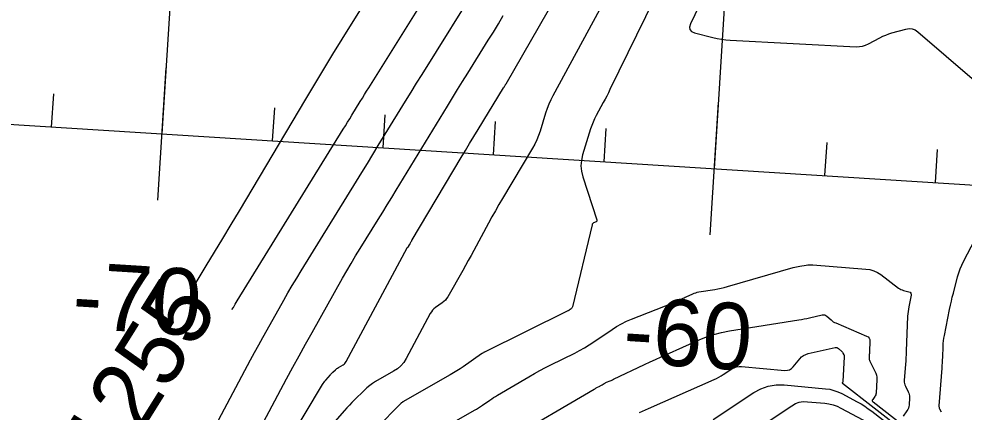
# Model space of a CAD drawing. Extents: x 658976 to 668721, y 639543 to 647196.
# Drawn here: x 662007.7 to 662093.1, y 641802.5 to 641838 of the extents above; entities that cross this region are included whole.
import ezdxf

# ---------------------------------------------------------------- set-up
doc = ezdxf.new("R2010")
doc.units = 0
for name, color, linetype in [('Ex_Contour Labels', 7, 'Continuous'), ('Ex_Major Contours', 7, 'Continuous'), ('Ex_Minor Contours', 7, 'Continuous'), ('R_Axis', 7, 'Continuous'), ('R_Axis Annot', 7, 'Continuous'), ('R_Grid', 7, 'Continuous')]:
    doc.layers.add(name, color=color, linetype=linetype)

msp = doc.modelspace()

# ---------------------------------------------------------------- linework, layer by layer
at = {"layer": 'Ex_Major Contours'}
for points in [[(662023.527, 641813.903), (662024.632, 641815.708), (662025.387, 641816.946), (662026.138, 641818.187), (662026.885, 641819.43), (662027.627, 641820.676), (662033.614, 641830.758), (662034.426, 641832.118), (662035.245, 641833.474), (662036.071, 641834.826), (662036.904, 641836.174), (662040.248, 641841.557)], [(662060.169, 641838.84), (662055.95, 641831.064), (662055.757, 641830.687), (662055.583, 641830.301), (662055.429, 641829.908), (662055.294, 641829.506), (662054.794, 641827.883), (662054.657, 641827.482), (662054.497, 641827.091), (662054.315, 641826.711), (662054.109, 641826.341), (662051.4, 641821.789), (662051.075, 641821.237), (662050.756, 641820.681), (662050.442, 641820.122), (662050.135, 641819.559), (662048.799, 641817.083), (662048.553, 641816.629), (662048.303, 641816.177), (662048.052, 641815.726), (662047.797, 641815.277), (662046.447, 641812.906), (662046.348, 641812.752), (662046.233, 641812.611), (662046.104, 641812.485), (662045.959, 641812.373), (662045.35, 641811.95), (662045.206, 641811.838), (662045.078, 641811.71), (662044.966, 641811.569), (662044.87, 641811.413), (662042.686, 641807.34), (662042.467, 641806.99), (662042.206, 641806.681), (662041.904, 641806.412), (662041.559, 641806.184), (662039.925, 641805.254), (662039.654, 641805.088), (662039.395, 641804.905), (662039.149, 641804.705), (662038.915, 641804.489), (662038.006, 641803.59), (662037.781, 641803.363), (662037.56, 641803.133), (662037.343, 641802.898), (662037.13, 641802.66), (662035.58, 641800.898)], [(662070.429, 641801.833), (662074.089, 641804.26), (662074.733, 641804.616), (662075.407, 641804.851), (662076.113, 641804.964), (662076.849, 641804.956), (662080.571, 641804.613), (662080.958, 641804.559), (662081.333, 641804.466), (662081.698, 641804.337), (662082.051, 641804.17), (662083.441, 641803.427), (662083.784, 641803.234), (662084.117, 641803.027), (662084.442, 641802.806), (662084.757, 641802.571), (662090.005, 641798.48)]]:
    msp.add_lwpolyline(points, dxfattribs=at)
at = {"layer": 'Ex_Minor Contours'}
for points in [[(662026.957, 641811.753), (662027.078, 641811.959), (662027.256, 641812.257), (662027.436, 641812.554), (662037.014, 641828.054), (662037.206, 641828.365), (662037.398, 641828.677), (662037.589, 641828.988), (662037.78, 641829.3), (662038.542, 641830.549), (662038.733, 641830.861), (662038.925, 641831.172), (662039.117, 641831.483), (662039.311, 641831.793), (662049.405, 641847.936)], [(662029.147, 641794.982), (662035.137, 641804.982), (662035.206, 641805.091), (662035.279, 641805.196), (662035.357, 641805.298), (662035.44, 641805.397), (662035.842, 641805.854), (662035.897, 641805.916), (662035.953, 641805.977), (662036.011, 641806.036), (662036.069, 641806.095), (662036.305, 641806.328), (662036.365, 641806.384), (662036.429, 641806.436), (662036.496, 641806.483), (662036.566, 641806.527), (662036.99, 641806.768), (662037.079, 641806.827), (662037.158, 641806.897), (662037.226, 641806.977), (662037.282, 641807.067), (662042.791, 641817.34), (662042.797, 641817.351), (662042.805, 641817.361), (662042.814, 641817.37), (662042.824, 641817.377), (662042.866, 641817.406), (662042.876, 641817.414), (662042.885, 641817.423), (662042.893, 641817.433), (662042.9, 641817.443), (662042.993, 641817.607), (662043.01, 641817.638), (662043.027, 641817.669), (662043.045, 641817.7), (662043.062, 641817.731), (662043.154, 641817.902), (662043.175, 641817.94), (662043.196, 641817.979), (662043.218, 641818.017), (662043.241, 641818.055), (662047.661, 641825.482), (662048.043, 641826.122), (662048.427, 641826.761), (662048.813, 641827.399), (662049.201, 641828.035), (662051.495, 641831.792), (662051.513, 641831.822), (662051.532, 641831.852), (662051.55, 641831.882), (662051.569, 641831.912), (662051.644, 641832.032), (662051.662, 641832.062), (662051.68, 641832.092), (662051.698, 641832.122), (662051.716, 641832.153), (662059.249, 641845.26)], [(662024.952, 641800.306), (662028.636, 641807.212), (662029.001, 641807.891), (662029.37, 641808.569), (662029.743, 641809.244), (662030.12, 641809.917), (662031.634, 641812.606), (662032.016, 641813.276), (662032.405, 641813.943), (662032.8, 641814.605), (662033.202, 641815.263), (662038.196, 641823.345), (662038.692, 641824.149), (662039.187, 641824.953), (662039.68, 641825.758), (662040.173, 641826.564), (662042.142, 641829.788), (662042.635, 641830.593), (662043.13, 641831.397), (662043.628, 641832.2), (662044.127, 641833.001), (662049.477, 641841.557)], [(662065.129, 641839.892), (662061.105, 641831.633), (662060.958, 641831.335), (662060.808, 641831.04), (662060.655, 641830.746), (662060.498, 641830.454), (662059.866, 641829.288), (662059.715, 641828.993), (662059.58, 641828.693), (662059.459, 641828.385), (662059.354, 641828.072), (662058.632, 641825.73), (662058.518, 641825.235), (662058.483, 641824.74), (662058.526, 641824.246), (662058.648, 641823.752), (662059.919, 641819.852), (662059.928, 641819.797), (662059.919, 641819.751), (662059.892, 641819.712), (662059.845, 641819.682), (662059.622, 641819.578), (662059.572, 641819.548), (662059.531, 641819.509), (662059.501, 641819.462), (662059.482, 641819.406), (662057.709, 641811.997), (662057.693, 641811.948), (662057.669, 641811.905), (662057.637, 641811.867), (662057.598, 641811.835), (662057.424, 641811.716), (662057.38, 641811.687), (662057.335, 641811.66), (662057.289, 641811.634), (662057.243, 641811.61), (662049.762, 641807.914), (662049.738, 641807.902), (662049.715, 641807.89), (662049.693, 641807.878), (662049.67, 641807.865), (662049.58, 641807.812), (662049.558, 641807.799), (662049.536, 641807.785), (662049.514, 641807.77), (662049.493, 641807.756), (662047.841, 641806.6), (662047.557, 641806.406), (662047.268, 641806.219), (662046.975, 641806.038), (662046.678, 641805.864), (662042.395, 641803.419), (662042.378, 641803.41), (662042.362, 641803.4), (662042.345, 641803.389), (662042.329, 641803.379), (662042.264, 641803.337), (662042.248, 641803.326), (662042.233, 641803.314), (662042.218, 641803.301), (662042.205, 641803.288), (662040.008, 641801.053)], [(662069.177, 641839.18), (662068.383, 641837.55), (662068.293, 641837.268), (662068.323, 641837.042), (662068.475, 641836.872), (662068.748, 641836.758), (662070.397, 641836.331), (662070.785, 641836.241), (662071.175, 641836.171), (662071.569, 641836.12), (662071.966, 641836.09), (662083.347, 641835.497), (662083.636, 641835.501), (662083.917, 641835.544), (662084.188, 641835.625), (662084.451, 641835.745), (662085.485, 641836.304), (662085.747, 641836.436), (662086.015, 641836.552), (662086.289, 641836.653), (662086.569, 641836.738), (662087.833, 641837.084), (662088.13, 641837.131), (662088.41, 641837.106), (662088.675, 641837.009), (662088.923, 641836.839), (662094.048, 641832.449)], [(662025.362, 641793.256), (662031.89, 641805.492), (662032.456, 641806.546), (662033.028, 641807.596), (662033.606, 641808.643), (662034.19, 641809.687), (662036.948, 641814.584), (662037.333, 641815.259), (662037.725, 641815.93), (662038.123, 641816.598), (662038.528, 641817.261), (662040.162, 641819.905), (662040.57, 641820.567), (662040.977, 641821.229), (662041.384, 641821.891), (662041.789, 641822.554), (662046.417, 641830.134), (662046.874, 641830.879), (662047.333, 641831.624), (662047.793, 641832.367), (662048.256, 641833.109), (662050.11, 641836.074), (662050.57, 641836.817), (662051.023, 641837.565), (662051.469, 641838.317)], [(662091.053, 641802.493), (662090.912, 641802.764), (662090.881, 641802.833), (662090.861, 641802.905), (662090.852, 641802.978), (662090.852, 641803.053), (662091.108, 641806.462), (662091.126, 641806.709), (662091.141, 641806.955), (662091.154, 641807.202), (662091.165, 641807.449), (662091.205, 641808.437), (662091.22, 641808.683), (662091.244, 641808.928), (662091.278, 641809.172), (662091.321, 641809.415), (662091.787, 641811.777), (662091.863, 641812.147), (662091.945, 641812.515), (662092.032, 641812.882), (662092.125, 641813.248), (662092.507, 641814.709), (662092.612, 641815.071), (662092.738, 641815.424), (662092.883, 641815.77), (662093.048, 641816.108), (662094.801, 641819.453)], [(662047.037, 641801.623), (662048.879, 641802.674), (662049.057, 641802.778), (662049.231, 641802.886), (662049.404, 641802.998), (662049.573, 641803.114), (662050.247, 641803.585), (662050.417, 641803.702), (662050.589, 641803.814), (662050.763, 641803.924), (662050.939, 641804.029), (662053.781, 641805.698), (662054.271, 641805.979), (662054.766, 641806.252), (662055.266, 641806.516), (662055.77, 641806.771), (662057.915, 641807.83), (662058.359, 641808.059), (662058.794, 641808.304), (662059.22, 641808.564), (662059.637, 641808.839), (662061.288, 641809.969), (662061.707, 641810.239), (662062.139, 641810.485), (662062.585, 641810.705), (662063.044, 641810.901), (662066.813, 641812.383), (662066.914, 641812.423), (662067.014, 641812.466), (662067.113, 641812.51), (662067.212, 641812.555), (662067.605, 641812.742), (662067.703, 641812.788), (662067.802, 641812.834), (662067.901, 641812.879), (662068, 641812.923), (662068.586, 641813.185), (662068.719, 641813.239), (662068.853, 641813.284), (662068.991, 641813.32), (662069.131, 641813.347), (662070.575, 641813.577), (662070.862, 641813.627), (662071.147, 641813.686), (662071.43, 641813.753), (662071.711, 641813.83), (662077.667, 641815.552), (662077.81, 641815.591), (662077.955, 641815.625), (662078.101, 641815.655), (662078.248, 641815.681), (662078.837, 641815.773), (662078.985, 641815.792), (662079.133, 641815.802), (662079.281, 641815.804), (662079.429, 641815.797), (662084.214, 641815.423), (662084.581, 641815.369), (662084.929, 641815.266), (662085.259, 641815.114), (662085.57, 641814.912), (662087.179, 641813.707), (662087.282, 641813.637), (662087.39, 641813.578), (662087.504, 641813.529), (662087.623, 641813.491), (662088.108, 641813.361), (662088.211, 641813.317), (662088.278, 641813.251), (662088.308, 641813.162), (662088.302, 641813.05), (662088.098, 641812.018), (662088.06, 641811.804), (662088.03, 641811.59), (662088.009, 641811.374), (662087.996, 641811.158), (662087.868, 641807.991), (662087.855, 641807.699), (662087.839, 641807.407), (662087.821, 641807.115), (662087.801, 641806.824), (662087.69, 641805.347), (662087.689, 641805.212), (662087.706, 641805.081), (662087.742, 641804.954), (662087.796, 641804.831), (662088.048, 641804.345), (662088.102, 641804.222), (662088.139, 641804.094), (662088.158, 641803.963), (662088.16, 641803.828), (662088.123, 641803.141), (662088.106, 641802.998), (662088.068, 641802.862), (662088.011, 641802.733), (662087.934, 641802.611), (662087.586, 641802.139)], [(662051.749, 641799.924), (662059.681, 641804.58), (662059.74, 641804.614), (662059.799, 641804.647), (662059.86, 641804.679), (662059.92, 641804.709), (662060.179, 641804.837), (662060.232, 641804.865), (662060.285, 641804.894), (662060.336, 641804.925), (662060.386, 641804.958), (662060.585, 641805.095), (662060.636, 641805.127), (662060.688, 641805.157), (662060.741, 641805.183), (662060.797, 641805.207), (662061.128, 641805.337), (662061.201, 641805.367), (662061.274, 641805.397), (662061.347, 641805.43), (662061.419, 641805.463), (662064.233, 641806.796), (662064.726, 641807.028), (662065.221, 641807.257), (662065.717, 641807.484), (662066.214, 641807.708), (662069.156, 641809.022), (662069.819, 641809.292), (662070.496, 641809.518), (662071.185, 641809.698), (662071.889, 641809.834), (662078.174, 641810.832), (662078.411, 641810.871), (662078.647, 641810.915), (662078.882, 641810.962), (662079.117, 641811.013), (662080.277, 641811.275), (662080.396, 641811.288), (662080.507, 641811.274), (662080.611, 641811.231), (662080.708, 641811.16), (662081.079, 641810.82), (662081.175, 641810.739), (662081.276, 641810.667), (662081.383, 641810.605), (662081.496, 641810.551), (662084.283, 641809.367), (662084.421, 641809.286), (662084.517, 641809.18), (662084.572, 641809.047), (662084.585, 641808.889), (662084.55, 641808.012), (662084.547, 641807.935), (662084.542, 641807.859), (662084.538, 641807.782), (662084.532, 641807.706), (662084.509, 641807.4), (662084.509, 641807.325), (662084.518, 641807.252), (662084.538, 641807.18), (662084.569, 641807.111), (662085.043, 641806.197), (662085.122, 641806.02), (662085.175, 641805.836), (662085.202, 641805.648), (662085.204, 641805.453), (662085.138, 641804.203), (662085.128, 641804.124), (662085.108, 641804.049), (662085.076, 641803.977), (662085.033, 641803.909), (662084.84, 641803.647), (662084.805, 641803.583), (662084.799, 641803.524), (662084.821, 641803.468), (662084.871, 641803.416), (662091.355, 641798.362)], [(662063.762, 641802.471), (662064.042, 641802.586), (662064.321, 641802.704), (662064.599, 641802.825), (662070.511, 641805.437), (662070.725, 641805.537), (662070.935, 641805.646), (662071.139, 641805.763), (662071.339, 641805.89), (662072.128, 641806.413), (662072.33, 641806.525), (662072.542, 641806.599), (662072.763, 641806.634), (662072.994, 641806.632), (662076.905, 641806.272), (662077.128, 641806.276), (662077.329, 641806.33), (662077.509, 641806.436), (662077.668, 641806.592), (662078.261, 641807.318), (662078.419, 641807.483), (662078.598, 641807.616), (662078.796, 641807.716), (662079.015, 641807.784), (662081.444, 641808.332), (662081.525, 641808.341), (662081.6, 641808.331), (662081.67, 641808.302), (662081.736, 641808.254), (662082.046, 641807.969), (662082.078, 641807.938), (662082.106, 641807.904), (662082.131, 641807.868), (662082.153, 641807.83), (662082.235, 641807.672), (662082.253, 641807.632), (662082.265, 641807.59), (662082.271, 641807.548), (662082.271, 641807.504), (662082.153, 641805.266), (662082.151, 641805.25), (662082.147, 641805.235), (662082.141, 641805.221), (662082.132, 641805.207), (662082.094, 641805.155), (662082.087, 641805.143), (662082.086, 641805.131), (662082.09, 641805.12), (662082.1, 641805.109), (662090.68, 641798.421)], [(662068.342, 641796.996), (662077.519, 641803.082), (662077.852, 641803.266), (662078.201, 641803.388), (662078.567, 641803.446), (662078.947, 641803.442), (662080.503, 641803.299), (662080.886, 641803.244), (662081.258, 641803.153), (662081.619, 641803.025), (662081.969, 641802.859), (662086.896, 641800.226)]]:
    msp.add_lwpolyline(points, dxfattribs=at)
at = {"layer": 'R_Axis'}
for p, q in [((661621.43, 641852.689), (663118.48, 641758.667)), ((662020.267, 641821.628), (662021.019, 641833.604)), ((662010.663, 641828.243), (662010.851, 641831.237)), ((662030.624, 641826.989), (662030.812, 641829.984)), ((662070.169, 641818.494), (662070.921, 641830.47)), ((662040.604, 641826.363), (662040.792, 641829.357)), ((662050.584, 641825.736), (662050.772, 641828.73)), ((662060.565, 641825.109), (662060.753, 641828.103)), ((662080.525, 641823.855), (662080.713, 641826.85)), ((662090.506, 641823.229), (662090.694, 641826.223))]:
    msp.add_line(p, q, dxfattribs=at)
at = {"layer": 'R_Grid'}
for p, q in [((662020.643, 641827.616), (662036.313, 642077.125)), ((662070.545, 641824.482), (662086.215, 642073.991)), ((661621.43, 641852.689), (663118.48, 641758.667))]:
    msp.add_line(p, q, dxfattribs=at)

# ---------------------------------------------------------------- texts
at = {"layer": 'Ex_Contour Labels'}
msp.add_text('1255', height=6, rotation=57.9151, dxfattribs=at).set_placement((662016.331, 641796.777))
at = {"layer": 'R_Axis Annot'}
for s, p in [('-70', (662012.421, 641810.097)), ('-60', (662062.181, 641806.972))]:
    msp.add_text(s, height=6, rotation=356.4063, dxfattribs=at).set_placement(p)

doc.saveas('drawing.dxf')
